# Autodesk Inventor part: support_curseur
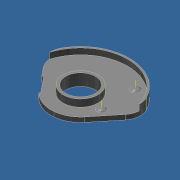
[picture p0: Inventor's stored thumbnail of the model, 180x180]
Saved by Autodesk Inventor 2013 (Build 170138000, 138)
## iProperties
Created: 2011-07
Part Number: support_curseur
Document SubType Name: Modeling
Designer: didierf
Density: 1.4 g/cm^3
Material: PVC-U
Mass: 0.16648 g
Surface Area: 3.90351 cm^2
Volume: 0.118915 cm^3
Author: didierf
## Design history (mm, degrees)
sketch "Esquisse3"
  geometry: L1 (-14.379, 11.345)-(1.25, 18.566); L2 (1.25, 18.566)-(10.479, -1.409); L3 (10.479, -1.409)-(-5.149, -8.63); L4 (-5.149, -8.63)-(-14.379, 11.345); L5 (4.506, -11.411)-(4.506, -32.563); 1 other entity
  constraints: 2 end point, 1 vertical, 2 other
  dimensions: "d19" = 17.216 distance of L1.start L1.end; "d84" = 24.7991 deg angle of L5 L4
  node "Image2"
sketch "tracé"
  geometry: L1 (3.886, -3.147)-(6.941, 0.626); L2 (0, -41.976)-(0, 8.25); L3 (-3.534, -3.184)-(-5.423, -0.851); L4 (-5.774, -0.814)-(-6.941, 0.626); L5 (0, 0)-(-3.552, -3.519); C1 r 2.5 at (0, 0); C2 r 0.5 at (4.25, -0.7); C3 r 0.5 at (4.25, 5.1); C4 r 2.95 at (0, 0); C5 r 1 at (3, 4); A1 r 5 centre (0, 0) between (-3.552, -3.519) and (3.886, -3.147); A2 r 8.25 centre (0, 0) between (7.243, 3.95) and (-7.243, 3.95); A3 r 3 centre (-4.609, 2.514) between (-7.243, 3.95) and (-6.941, 0.626); A4 r 3 centre (4.609, 2.514) between (6.941, 0.626) and (7.243, 3.95); A5 r 0.25 centre (-3.728, -3.341) between (-3.552, -3.519) and (-3.534, -3.184); A6 r 0.25 centre (-5.617, -1.009) between (-5.423, -0.851) and (-5.774, -0.814); A7 r 7.95 centre (0, 0) between (7.603, 2.323) and (-7.603, 2.323); 1 further point
  constraints: 17 point on circle, 12 centre point, 10 end point, 9 tangent, 5 coincident, 1 parallel, 1 point on line, 1 vertical
  dimensions: "d53" = 10 diameter of A1; "d54" = 5 diameter of C1; "d57" = 8.25 radius of A2; "d60" = 6 diameter of A3; "d61" = 6 diameter of A4; "d66" = 78 deg angle of L1 L4; "d67" = 0.25 radius of A5; "d68" = 0.25 radius of A6; "d69" = 0.25 distance between parallel lines of L4 L3; "d70" = 3.5 distance of L4.start L5.end; "d71" = 39 deg angle of L1 L2 (derived); "d104" = 1 diameter of C2; "d105" = 1 diameter of C3; "d106" = 4.25 horizontal distance of C2.centre point (0, 0); "d107" = 0.7 vertical distance of C2.centre point (0, 0); "d108" = 5.8 distance of C2.centre C3.centre; "d109" = 4.25 horizontal distance of C3.centre point (0, 0) (derived); "d110" = 0.3 radial gap between concentric circles of A7 A2; "d114" = 5.9 diameter of C4; "d115" = 2 diameter of C5; "d117" = 3 distance from line of C5.centre L2; "d120" = 4 vertical distance of C5.centre point (0, 0)
extrude "embase" new body sketch "tracé" distance "d122" = 0.8; taper "d123" = 0 deg
extrude "bossage central" join sketch "tracé" distance "d124" = 1.2; taper "d125" = 0 deg
extrude "plotSertissage1" join sketch "tracé" distance "d126" = 1; taper "d127" = 0 deg
extrude "plotSertissage2" join sketch "tracé" distance "d128" = 0.1; taper "d129" = 0 deg
node "Plan de construction1"
  node "Axe de construction1"
  node "Axe de construction2"
sketch "sertissage"
  geometry: L1 (-1.2, 5.8)-(1.6, 5.8) reference; L2 (0.1, 6.3)-(0.1, 5.3) reference; L3 (0.4, 4.925)-(0.4, 6.54); L4 (0.1, 5.05)-(0.1, 6.55); L5 (0.1, 0.5)-(0.1, -0.5) reference; L6 (0.4, 1.009)-(0.4, -1.186); L7 (-1.2, 0)-(1.6, 0) reference; L8 (0.1, 0)-(0.1, -0.75); L9 (0.1, 0)-(0.1, 0.75); L10 (0.4, 5.8)-(0.1, 5.8); L11 (0.4, 0)-(0.1, 0); A1 r 1.088 centre (-0.687, 5.8) between (0.1, 5.05) and (0.4, 5.8); A2 r 1.088 centre (-0.688, 0) between (0.1, -0.75) and (0.4, 0)
  constraints: 14 end point, 7 point on line, 4 point on circle, 3 parallel, 2 centre point, 2 collinear, 2 midpoint
  dimensions: "d130" = 0.3 distance between parallel lines of L2 L3; "d131" = 0.75 distance from line of L4.start L1; "d132" = 1.5 distance of L4.start L4.end; "d133" = 1.0875 radius of A1; "d134" = 0.3 distance between parallel lines of L6 L5 (derived); "d135" = 0.75 distance of L8.start L8.end; "d136" = 0.75 distance of L8.start L9.end; "d137" = 1.0875 radius of A2
revolve "plot1" stored, may be unused: angle "d138" = 90 deg
revolve "plot2" stored, may be unused: angle "d139" = 90 deg
node "Plan de construction2"
extrude "plot3" join sketch "tracé" stored distance "d141" = 0.1; taper "d142" = 0 deg
node "Solide1"
node "Corps solides"
node "Corps surfaciques"
fillet "congé" dims "d143" = 0.5
other parameters: "d52" = 78 deg, "d62" = 0.25, "d63" = 0.25, "d140" = -3.2
